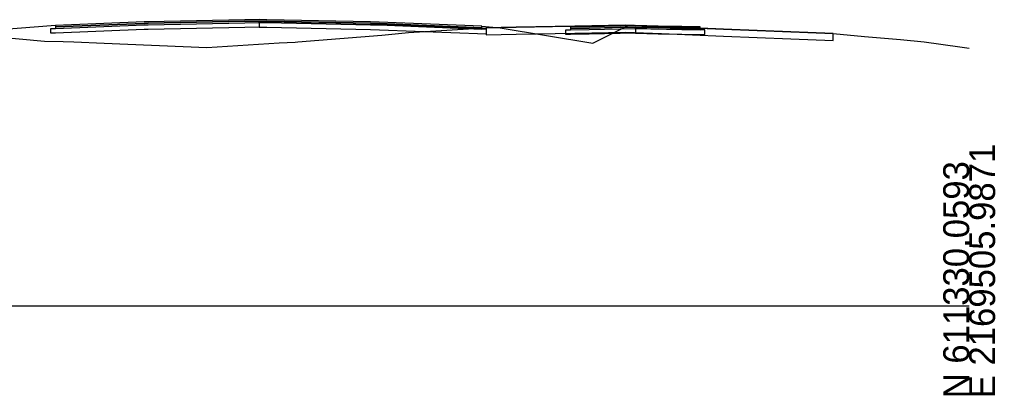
# Model space of a CAD drawing. Extents: x -26 to 1303, y -3010 to 12038.
# Drawn here: x 1197.5 to 1302.8, y 4990.3 to 5030.9 of the extents above; entities that cross this region are included whole.
import ezdxf

# ---------------------------------------------------------------- set-up
doc = ezdxf.new("R2010")
doc.units = 0
for name, color, linetype in [('RD_GPK_XS_Cell', 7, 'Continuous'), ('RD_XS_Base', 7, 'Continuous'), ('RD_XS_ExGround', 7, 'Continuous'), ('RD_XS_ExPaveRet', 7, 'Continuous'), ('RD_XS_Greenside', 7, 'Continuous'), ('RD_XS_Pave', 7, 'Continuous'), ('RD_XS_PaveOvlay_CP', 7, 'Continuous'), ('RD_XS_TieSlope', 7, 'Continuous')]:
    doc.layers.add(name, color=color, linetype=linetype)

msp = doc.modelspace()

# ---------------------------------------------------------------- linework, layer by layer
at = {"layer": 'RD_GPK_XS_Cell'}
msp.add_line((1150, 5000), (1300, 5000), dxfattribs=at)
at = {"layer": 'RD_XS_Base'}
for p, q in [((1201.38, 5029.94), (1210.95, 5030.32)), ((1210.95, 5030.32), (1211.38, 5030.34)), ((1211.38, 5030.34), (1221.83, 5030.55)), ((1221.83, 5030.55), (1223.38, 5030.58)), ((1223.38, 5030.73), (1223.38, 5030.74)), ((1223.38, 5030.74), (1223.38, 5030.7)), ((1223.38, 5030.58), (1223.38, 5030.73)), ((1223.38, 5030.7), (1223.38, 5030.08)), ((1223.38, 5030.58), (1223.38, 5030.55)), ((1223.38, 5030.58), (1223.38, 5030.58)), ((1224.19, 5030.57), (1223.38, 5030.58)), ((1223.38, 5030.58), (1223.38, 5030.58)), ((1223.38, 5030.55), (1223.38, 5030.08)), ((1235.38, 5030.34), (1224.19, 5030.57)), ((1236.32, 5030.31), (1235.38, 5030.34)), ((1247.39, 5029.86), (1236.32, 5030.31)), ((1200.88, 5029.92), (1201.37, 5029.94)), ((1200.88, 5029.9), (1200.88, 5029.92)), ((1200.88, 5029.42), (1200.88, 5029.9)), ((1201.37, 5029.44), (1200.88, 5029.42)), ((1201.37, 5029.94), (1201.38, 5029.94)), ((1201.38, 5029.44), (1201.37, 5029.44)), ((1210.95, 5029.82), (1201.38, 5029.44)), ((1211.38, 5029.84), (1210.95, 5029.82)), ((1221.83, 5030.05), (1211.38, 5029.84)), ((1223.38, 5030.08), (1221.83, 5030.05)), ((1223.38, 5030.08), (1224.19, 5030.07)), ((1224.19, 5030.07), (1235.38, 5029.84)), ((1235.38, 5029.84), (1236.36, 5029.8)), ((1236.36, 5029.8), (1247.89, 5029.34)), ((1247.43, 5029.86), (1247.39, 5029.86)), ((1247.89, 5029.84), (1247.43, 5029.86)), ((1247.89, 5029.8), (1247.89, 5029.84)), ((1247.89, 5029.34), (1247.89, 5029.8)), ((1256.47, 5029.77), (1256.97, 5029.78)), ((1256.47, 5029.27), (1256.47, 5029.77)), ((1256.97, 5029.28), (1256.47, 5029.27)), ((1256.97, 5029.78), (1258.97, 5029.82)), ((1258.97, 5029.32), (1256.97, 5029.28)), ((1258.97, 5029.82), (1263.97, 5029.92)), ((1263.97, 5029.42), (1258.97, 5029.32)), ((1263.97, 5030), (1263.97, 5030.08)), ((1263.97, 5030.08), (1263.97, 5029.75)), ((1263.97, 5029.92), (1263.97, 5030)), ((1266.43, 5029.87), (1263.97, 5029.92)), ((1263.97, 5029.92), (1263.97, 5029.42)), ((1263.97, 5029.75), (1263.97, 5029.42)), ((1263.97, 5029.42), (1266.43, 5029.37)), ((1268.97, 5029.82), (1266.43, 5029.87)), ((1266.43, 5029.37), (1268.97, 5029.32)), ((1270, 5029.8), (1268.97, 5029.82)), ((1268.97, 5029.32), (1270.18, 5029.29)), ((1270.97, 5029.78), (1270, 5029.8)), ((1270.18, 5029.29), (1271.47, 5029.27)), ((1271.21, 5029.77), (1270.97, 5029.78)), ((1271.47, 5029.77), (1271.21, 5029.77)), ((1271.47, 5029.51), (1271.47, 5029.77)), ((1271.47, 5029.27), (1271.47, 5029.51))]:
    msp.add_line(p, q, dxfattribs=at)
at = {"layer": 'RD_XS_ExGround'}
msp.add_lwpolyline([(1185.3, 5029.93), (1200.21, 5028.56), (1202.22, 5028.51), (1203.37, 5028.5), (1206.62, 5028.34), (1217.73, 5027.87), (1225.53, 5028.37), (1227.26, 5028.45), (1227.52, 5028.49), (1236.61, 5029.2), (1239.5, 5029.51), (1247.15, 5029.96), (1247.85, 5029.99), (1251.11, 5030.06), (1262.91, 5030.3), (1273.5, 5029.86), (1285.33, 5029.39), (1288.7, 5029.05), (1292.57, 5028.73), (1295.15, 5028.5), (1299, 5027.95), (1300, 5027.8)], dxfattribs=at)
at = {"layer": 'RD_XS_ExPaveRet'}
for p, q in [((1257.43, 5030.19), (1251.11, 5030.06)), ((1262.91, 5030.3), (1257.43, 5030.19)), ((1266.79, 5030.14), (1262.91, 5030.3)), ((1273.5, 5029.86), (1266.79, 5030.14)), ((1280.76, 5029.57), (1273.5, 5029.86))]:
    msp.add_line(p, q, dxfattribs=at)
for points in [[(1280.76, 5029.57), (1273.5, 5029.86), (1266.79, 5030.14), (1262.91, 5030.3), (1257.43, 5030.19), (1251.11, 5030.06), (1247.85, 5029.99), (1247.85, 5029.99), (1247.85, 5029.99), (1247.85, 5029.99), (1247.85, 5029.99), (1247.85, 5029.7), (1247.85, 5029.24), (1247.85, 5029.24), (1247.85, 5029.24), (1247.85, 5029.24), (1247.85, 5029.24), (1251.11, 5029.31), (1257.43, 5029.44), (1262.91, 5029.55), (1266.79, 5029.39), (1273.5, 5029.11), (1280.76, 5028.82), (1285.33, 5028.64), (1285.33, 5028.98), (1285.33, 5029.39), (1280.76, 5029.57)], [(1251.11, 5030.06), (1247.85, 5029.99), (1247.85, 5029.99), (1247.85, 5029.99), (1247.85, 5029.99), (1247.85, 5029.99)], [(1247.85, 5029.99), (1247.85, 5029.7), (1247.85, 5029.24), (1247.85, 5029.24), (1247.85, 5029.24), (1247.85, 5029.24), (1251.11, 5029.31), (1257.43, 5029.44), (1262.91, 5029.55), (1266.79, 5029.39), (1273.5, 5029.11), (1280.76, 5028.82), (1285.33, 5028.64), (1285.33, 5028.98), (1285.33, 5029.39), (1280.76, 5029.57)]]:
    msp.add_lwpolyline(points, dxfattribs=at)
at = {"layer": 'RD_XS_Greenside'}
for p, q in [((1259.39, 5028.36), (1263.25, 5030.29)), ((1249.39, 5030.02), (1259.39, 5028.36))]:
    msp.add_line(p, q, dxfattribs=at)
at = {"layer": 'RD_XS_Pave'}
for p, q in [((1210.95, 5030.64), (1201.38, 5030.26)), ((1210.95, 5030.48), (1201.38, 5030.1)), ((1201.38, 5030.1), (1210.95, 5030.48)), ((1201.38, 5029.94), (1210.95, 5030.32)), ((1201.38, 5030.26), (1201.38, 5030.25)), ((1201.38, 5030.25), (1201.38, 5030.1)), ((1211.38, 5030.66), (1210.95, 5030.64)), ((1211.38, 5030.5), (1210.95, 5030.48)), ((1210.95, 5030.48), (1211.38, 5030.5)), ((1210.95, 5030.32), (1211.38, 5030.34)), ((1221.83, 5030.87), (1211.38, 5030.66)), ((1221.83, 5030.71), (1211.38, 5030.5)), ((1211.38, 5030.5), (1221.83, 5030.71)), ((1211.38, 5030.34), (1221.83, 5030.55)), ((1223.38, 5030.9), (1221.83, 5030.87)), ((1223.38, 5030.74), (1221.83, 5030.71)), ((1221.83, 5030.71), (1223.38, 5030.74)), ((1221.83, 5030.55), (1223.38, 5030.58)), ((1224.19, 5030.88), (1223.38, 5030.9)), ((1223.38, 5030.73), (1223.38, 5030.74)), ((1223.38, 5030.74), (1224.19, 5030.73)), ((1224.19, 5030.73), (1223.38, 5030.74)), ((1223.38, 5030.74), (1223.38, 5030.74)), ((1223.38, 5030.74), (1223.38, 5030.74)), ((1223.38, 5030.74), (1223.38, 5030.73)), ((1223.38, 5030.58), (1223.38, 5030.73)), ((1223.38, 5030.73), (1223.38, 5030.58)), ((1223.38, 5030.58), (1223.38, 5030.58)), ((1223.38, 5030.58), (1223.38, 5030.58)), ((1223.38, 5030.58), (1224.19, 5030.57)), ((1235.38, 5030.66), (1224.19, 5030.88)), ((1224.19, 5030.73), (1235.38, 5030.5)), ((1235.38, 5030.5), (1224.19, 5030.73)), ((1224.19, 5030.57), (1235.38, 5030.34)), ((1236.32, 5030.62), (1235.38, 5030.66)), ((1235.38, 5030.5), (1236.32, 5030.46)), ((1236.32, 5030.46), (1235.38, 5030.5)), ((1235.38, 5030.34), (1236.32, 5030.31)), ((1247.39, 5030.18), (1236.32, 5030.62)), ((1236.32, 5030.46), (1247.39, 5030.02)), ((1247.39, 5030.02), (1236.32, 5030.46)), ((1236.32, 5030.31), (1247.39, 5029.86)), ((1247.39, 5030.17), (1247.39, 5030.18)), ((1247.39, 5030.02), (1247.39, 5030.17)), ((1261.45, 5030.19), (1258.97, 5030.14)), ((1263.97, 5030.24), (1261.45, 5030.19)), ((1266.43, 5030.19), (1263.97, 5030.24)), ((1268.97, 5030.14), (1266.43, 5030.19)), ((1201.38, 5030.1), (1201.38, 5030.1)), ((1201.38, 5030.1), (1201.38, 5029.94)), ((1247.39, 5030.01), (1247.39, 5030.02)), ((1247.39, 5029.86), (1247.39, 5030.01)), ((1257.94, 5030.12), (1256.97, 5030.1)), ((1256.97, 5030.1), (1256.97, 5030.01)), ((1256.97, 5030.01), (1256.97, 5029.94)), ((1258.97, 5029.98), (1256.97, 5029.94)), ((1256.97, 5029.94), (1257.99, 5029.96)), ((1256.97, 5029.94), (1256.97, 5029.78)), ((1256.97, 5029.78), (1258.97, 5029.82)), ((1258.97, 5030.14), (1257.94, 5030.12)), ((1257.99, 5029.96), (1258.97, 5029.98)), ((1263.97, 5030.08), (1258.97, 5029.98)), ((1258.97, 5029.98), (1261.45, 5030.03)), ((1258.97, 5029.82), (1263.97, 5029.92)), ((1261.45, 5030.03), (1263.97, 5030.08)), ((1263.97, 5030.08), (1266.43, 5030.03)), ((1268.97, 5029.98), (1263.97, 5030.08)), ((1263.97, 5030.08), (1263.97, 5029.92)), ((1263.97, 5029.92), (1263.97, 5030.08)), ((1263.97, 5029.92), (1268.97, 5029.82)), ((1266.43, 5030.03), (1268.97, 5029.98)), ((1270, 5030.12), (1268.97, 5030.14)), ((1268.97, 5029.98), (1269.94, 5029.96)), ((1270.97, 5029.94), (1268.97, 5029.98)), ((1268.97, 5029.82), (1270.97, 5029.78)), ((1269.94, 5029.96), (1270.97, 5029.94)), ((1270.97, 5030.1), (1270, 5030.12)), ((1270.97, 5030.01), (1270.97, 5030.1)), ((1270.97, 5029.94), (1270.97, 5030.01)), ((1270.97, 5029.78), (1270.97, 5029.94))]:
    msp.add_line(p, q, dxfattribs=at)
at = {"layer": 'RD_XS_PaveOvlay_CP'}
for p, q in [((1210.95, 5030.64), (1201.38, 5030.26)), ((1211.38, 5030.66), (1210.95, 5030.64)), ((1221.83, 5030.87), (1211.38, 5030.66)), ((1223.38, 5030.9), (1221.83, 5030.87)), ((1224.19, 5030.88), (1223.38, 5030.9)), ((1235.38, 5030.66), (1224.19, 5030.88)), ((1236.32, 5030.62), (1235.38, 5030.66)), ((1247.39, 5030.18), (1236.32, 5030.62)), ((1258.97, 5030.14), (1263.97, 5030.24)), ((1263.97, 5030.24), (1268.97, 5030.14)), ((1256.97, 5030.1), (1258.97, 5030.14)), ((1268.97, 5030.14), (1270.97, 5030.1))]:
    msp.add_line(p, q, dxfattribs=at)
at = {"layer": 'RD_XS_TieSlope'}
for p, q in [((1201.38, 5030.26), (1195.38, 5029.78)), ((1247.39, 5030.18), (1249.39, 5030.02))]:
    msp.add_line(p, q, dxfattribs=at)

# ---------------------------------------------------------------- texts
at = {"layer": 'RD_GPK_XS_Cell'}
for s, p in [('E 2169505.9871', (1302.8, 4990)), ('N 611330.0593', (1300, 4990))]:
    msp.add_text(s, height=2.8, rotation=90, dxfattribs=at).set_placement(p)

doc.saveas('drawing.dxf')
